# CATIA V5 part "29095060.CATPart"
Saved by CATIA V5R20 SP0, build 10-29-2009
Part number: 29095060
Definition: NONE
Nomenclature: 29095060
Source: Unknown
Description: 29095060
Bounding box of the stored display mesh (mm): x -30 to 44.548, y -61.5 to 96.048, z -51.5 to 51.5
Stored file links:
  C:\Users\Utente\Desktop\IO LAVORO\3D X SITO CF\X SITO\PLASTICA\RF1\29095060.CATPart
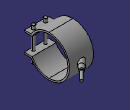
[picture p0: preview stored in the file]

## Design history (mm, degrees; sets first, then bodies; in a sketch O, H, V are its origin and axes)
Body1 "29095060" (main body)
  Solid1: solid without history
